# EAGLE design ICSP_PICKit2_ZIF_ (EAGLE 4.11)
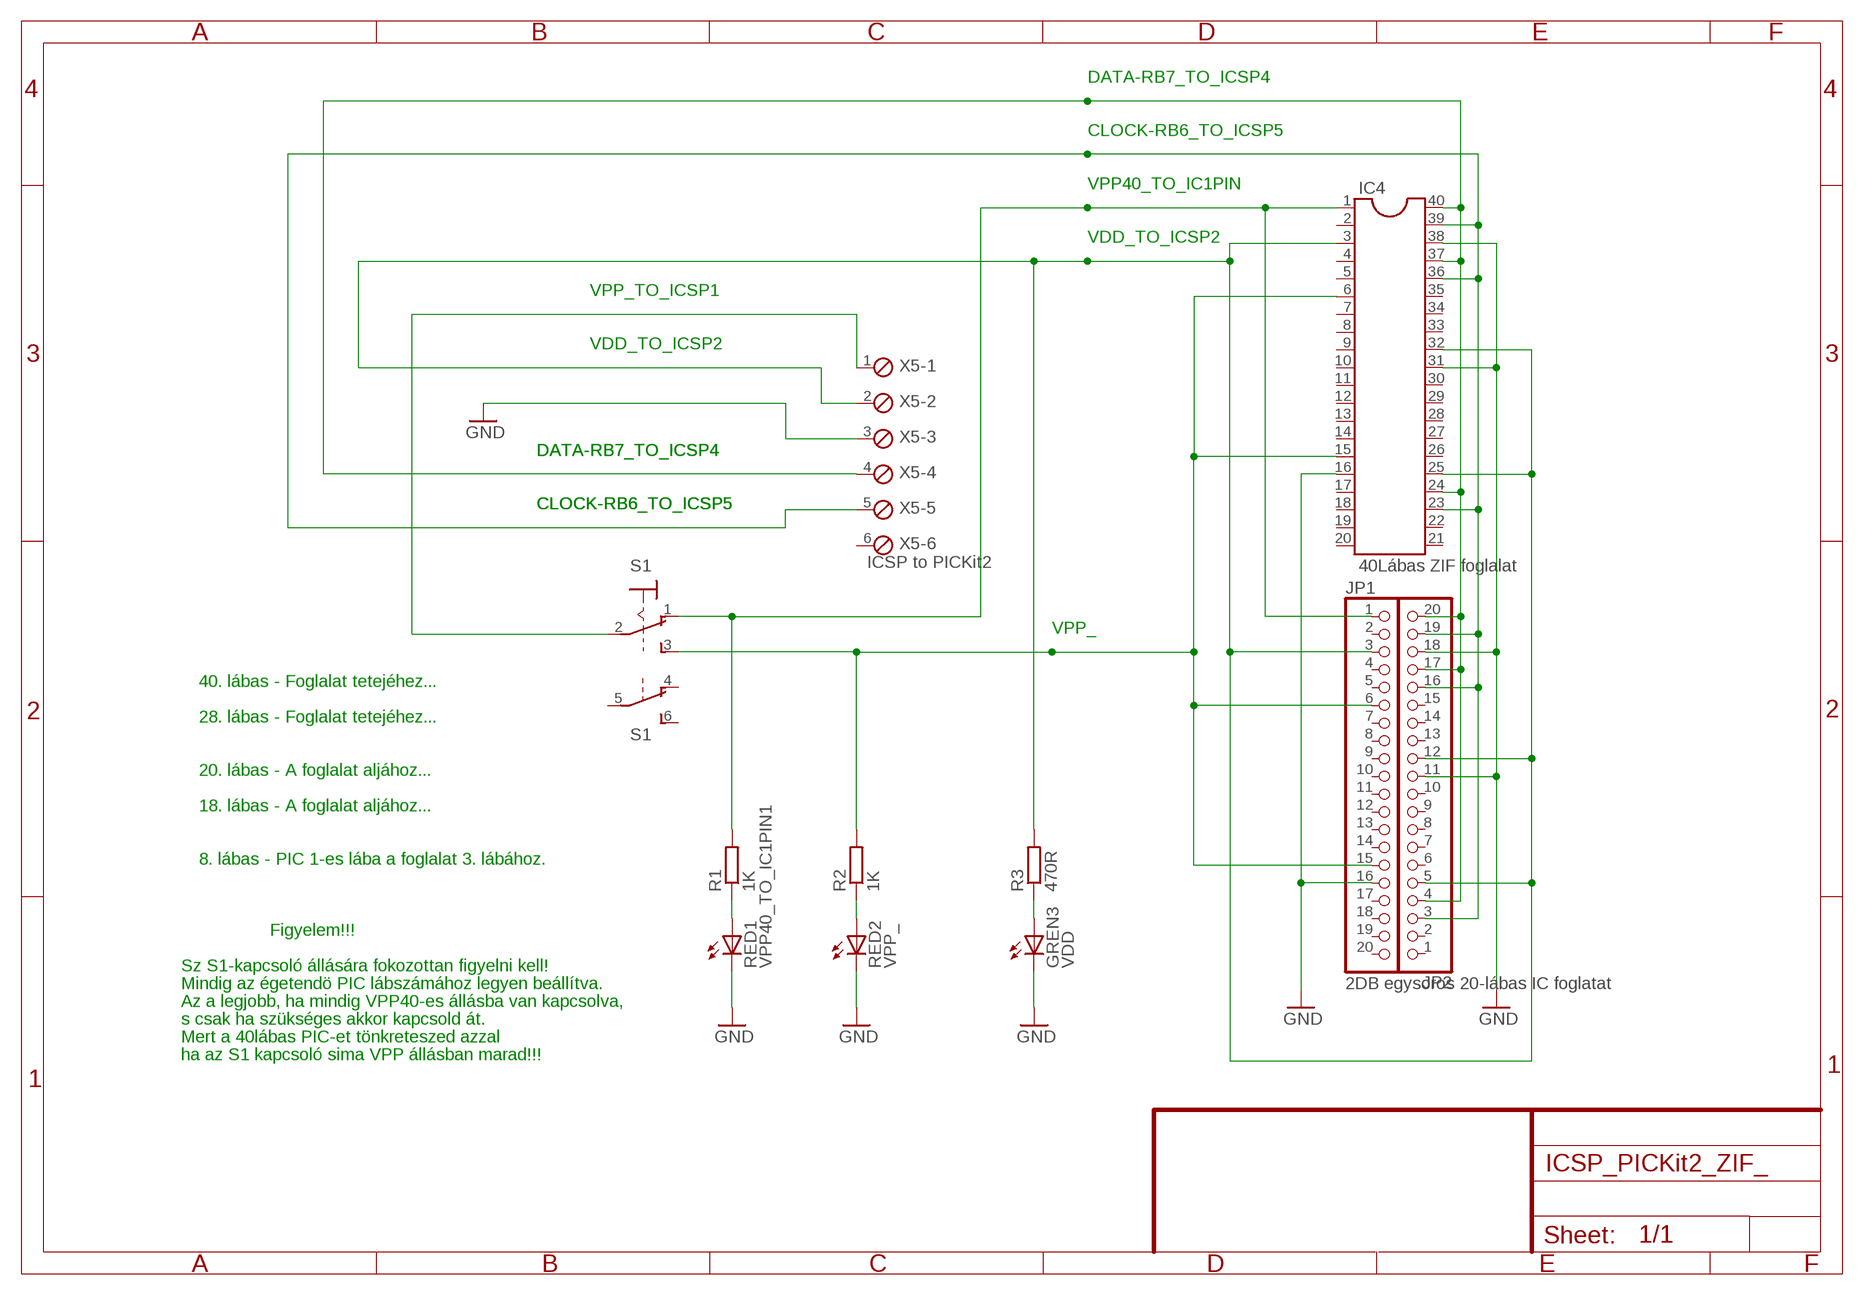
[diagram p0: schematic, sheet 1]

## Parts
GREN3  VDD  LED3MM  [LED3MM]
IC4  40Lábas ZIF foglalat  DIL40  [DIL40]
JP1  2DB egysoros 20-lábas IC foglatat  PINHD-1X20  [1X20]
JP2  PINHD-1X20  [1X20]
R1  1K  R-EU_0204/7  [0204/7]
R2  1K  R-EU_0204/7  [0204/7]
R3  470R  R-EU_0204/7  [0204/7]
RED1  VPP40_TO_IC1PIN1  LED3MM  [LED3MM]
RED2  VPP_  LED3MM  [LED3MM]
S1  320-938  [320-938]
X5  ICSP to PICKit2  MPT6  [6POL254]

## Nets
GND: GREN3.K(C) IC4.16 IC4.31 IC4.38 JP1.16 JP2.11 JP2.18 RED1.K(C) RED2.K(C) X5.3
N$2: IC4.3 IC4.25 IC4.32 JP1.3 JP2.5 JP2.12 R3.2 X5.2
N$5: S1.2(1:P) X5.1
N$6: IC4.1 JP1.1 R1.2 S1.1(1:O)
N$7: IC4.6 IC4.15 JP1.6 JP1.15 R2.2 S1.3(1:S)
N$8: R1.1 RED1.A
N$9: R2.1 RED2.A
N$10: GREN3.A R3.1
N$39: IC4.23 IC4.36 IC4.39 JP2.3 JP2.16 JP2.19 X5.5
N$40: IC4.24 IC4.37 IC4.40 JP2.4 JP2.17 JP2.20 X5.4
Unconnected: IC4.2 IC4.4 IC4.5 IC4.7 IC4.8 IC4.9 IC4.10 IC4.11 IC4.12 IC4.13 IC4.14 IC4.17 IC4.18 IC4.19 IC4.20 IC4.21 IC4.22 IC4.26 IC4.27 IC4.28 IC4.29 IC4.30 IC4.33 IC4.34 IC4.35 JP1.2 JP1.4 JP1.5 JP1.7 JP1.8 JP1.9 JP1.10 JP1.11 JP1.12 JP1.13 JP1.14 JP1.17 JP1.18 JP1.19 JP1.20 JP2.1 JP2.2 JP2.6 JP2.7 JP2.8 JP2.9 JP2.10 JP2.13 JP2.14 JP2.15 S1.4(B:O) S1.5(B:P) S1.6(B:S) X5.6

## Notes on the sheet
- DATA-RB7_TO_ICSP4
- CLOCK-RB6_TO_ICSP5
- VPP40_TO_IC1PIN
- VDD_TO_ICSP2
- VPP_TO_ICSP1
- VDD_TO_ICSP2
- DATA-RB7_TO_ICSP4 | DATA-RB7_TO_ICSP4
- CLOCK-RB6_TO_ICSP5 | CLOCK-RB6_TO_ICSP5 | CLOCK-RB6_TO_ICSP5
- VPP_
- 40. lábas - Foglalat tetejéhez...
- 28. lábas - Foglalat tetejéhez...
- 20. lábas - A foglalat aljához...
- 18. lábas - A foglalat aljához...
- 8. lábas - PIC 1-es lába a foglalat 3. lábához.
- Figyelem!!!
- Sz S1-kapcsoló állására fokozottan figyelni kell!
- Mindig az égetendö PIC lábszámához legyen beállítva.
- Az a legjobb, ha mindig VPP40-es állásba van kapcsolva,
- s csak ha szükséges akkor kapcsold át.
- Mert a 40lábas PIC-et tönkreteszed azzal
- ha az S1 kapcsoló sima VPP állásban marad!!!

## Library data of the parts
GREN3 RED1 RED2 = led:LED: LED
IC4 = ic-package:DIL40: Dual In Line
JP1 JP2 = pinhead:PINHD-1X20: PIN HEADER
R1-R3 = rcl:R-EU_: RESISTOR, European symbol
S1 = switch:320-938: TOGGLE SWITCH distributor RS Components
X5 = con-phoenix-254:MPT6: PHOENIX CONNECTOR

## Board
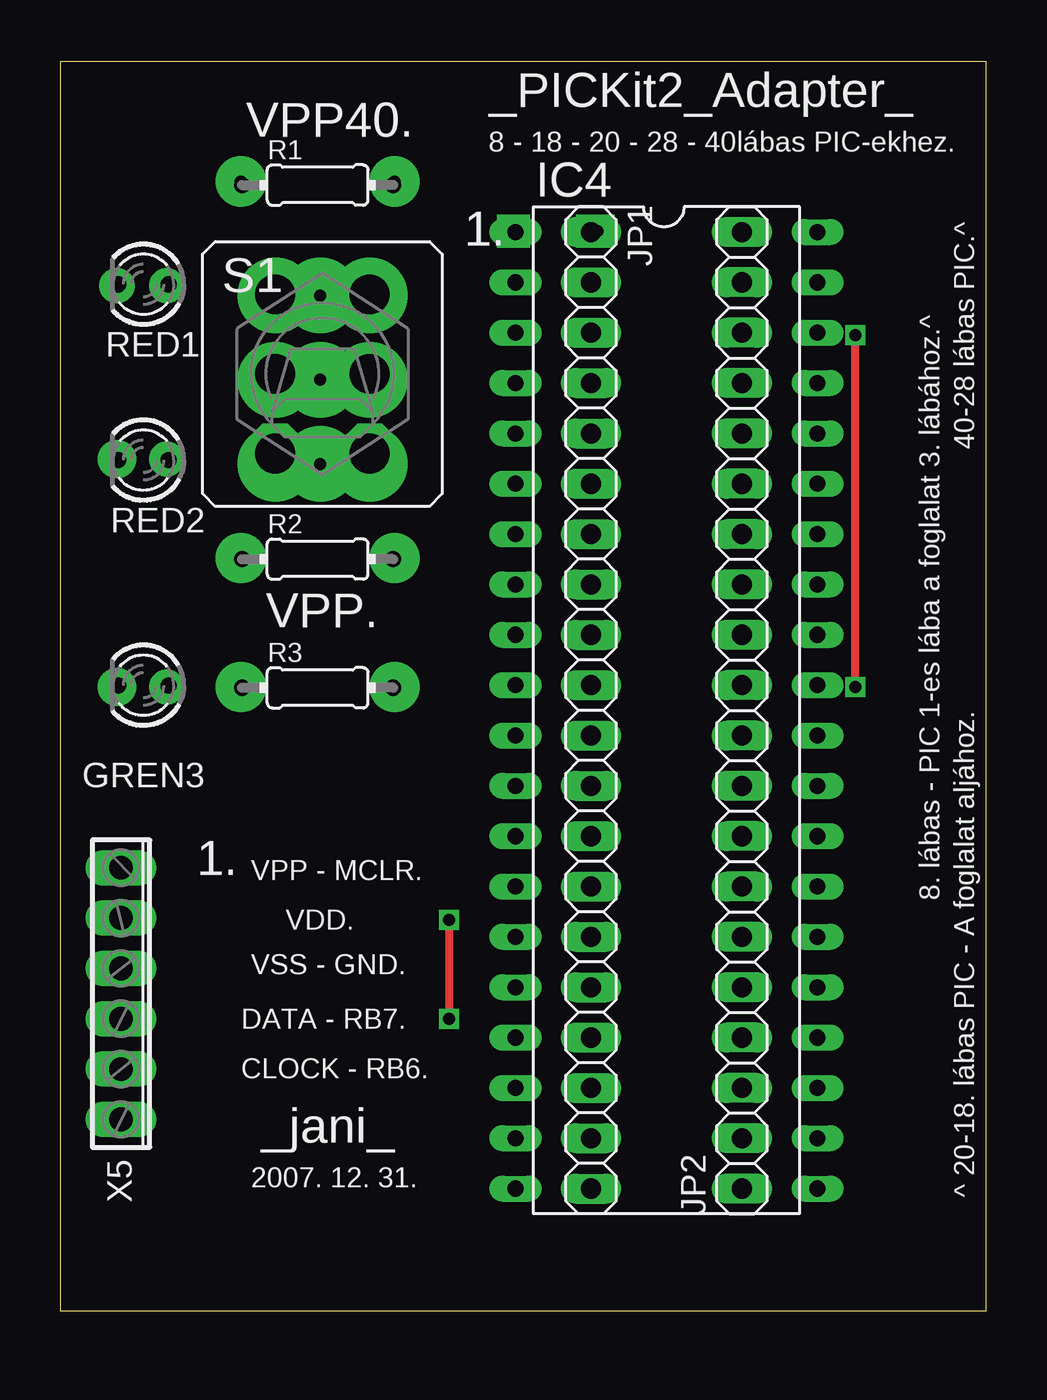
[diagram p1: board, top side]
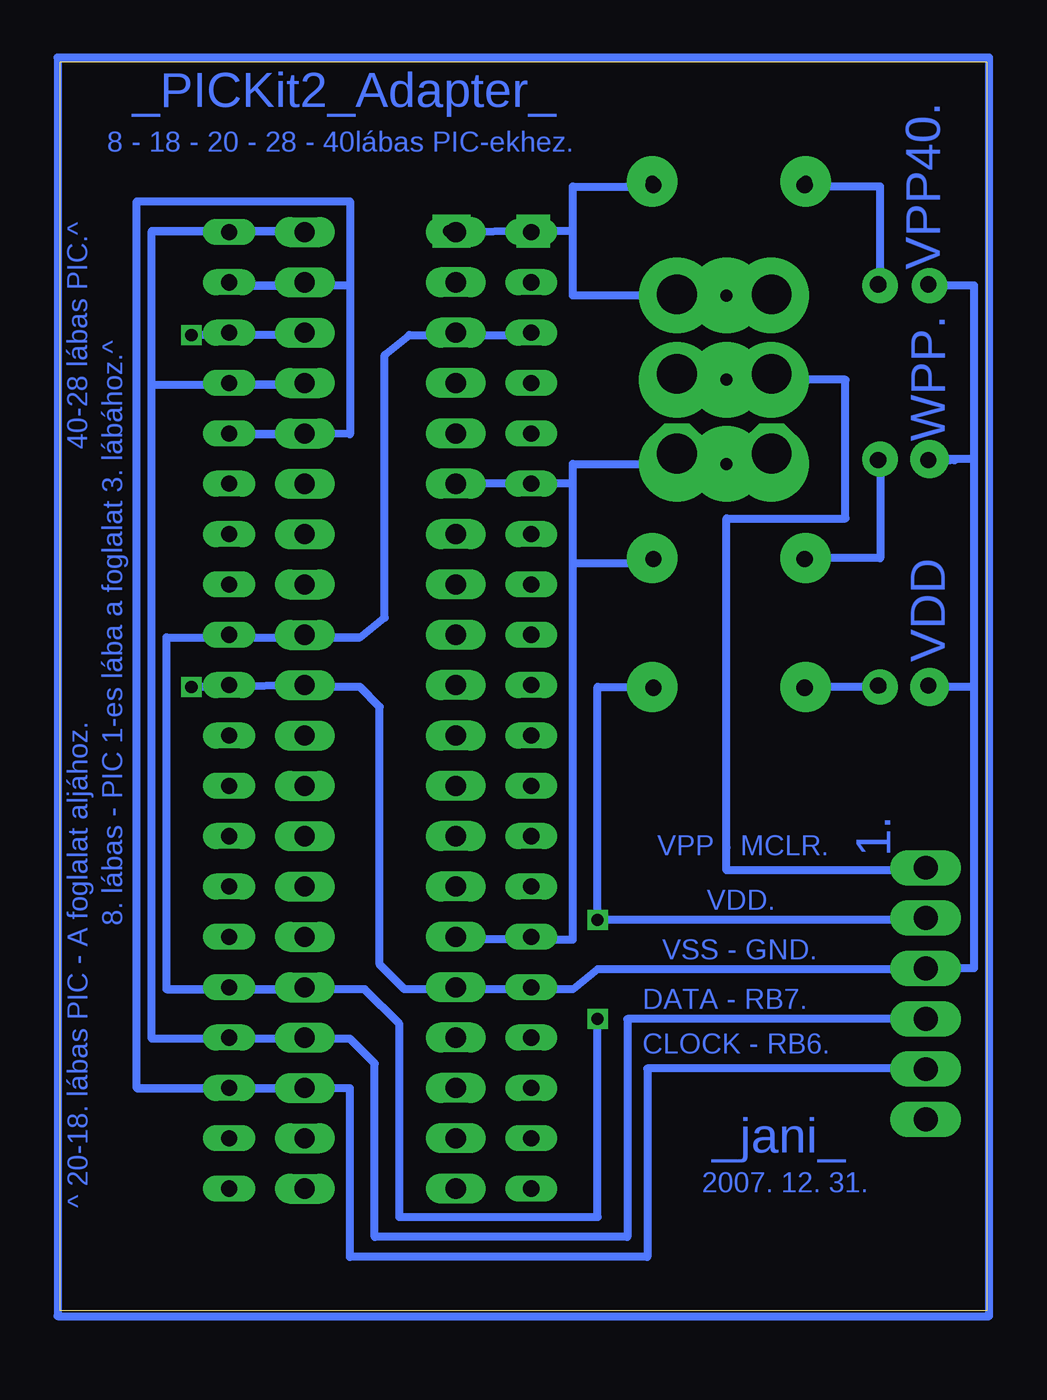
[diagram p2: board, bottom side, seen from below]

Size 46.74 x 63 mm. Coordinates in mm from the lower left corner, seen from the top.
Outline: 0,0 46.74,0 46.74,63 0,63 0,0
Copper layers (1*16): Top 0.035mm / dielectric 1.5mm / Bottom 0.035mm
Design rules "default": minimum track width 10mil, minimum drill 24mil, track to track 8mil, track to pad 8mil, pad to pad 8mil, via to via 8mil, smd to smd 8mil, copper to edge 40mil, drill to drill 8mil, minimum pad ring 10mil, minimum via ring 8mil, stop-mask expansion 4mil, vias tented up to drill 0mil, thermal gap 10mil

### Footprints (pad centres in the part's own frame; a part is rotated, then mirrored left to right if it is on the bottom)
LED3MM = drill 0.813 octagon: A -1.27,0; K 1.27,0
DIL40 = drill 0.813 long: 1 -24.13,-7.62; 2 -21.59,-7.62; 3 -19.05,-7.62; 4 -16.51,-7.62; 5 -13.97,-7.62; 6 -11.43,-7.62; 7 -8.89,-7.62; 8 -6.35,-7.62; 9 -3.81,-7.62; 10 -1.27,-7.62; 11 1.27,-7.62; 12 3.81,-7.62; 13 6.35,-7.62; 14 8.89,-7.62; 15 11.43,-7.62; 16 13.97,-7.62; 17 16.51,-7.62; 18 19.05,-7.62; 19 21.59,-7.62; 20 24.13,-7.62; 21 24.13,7.62; 22 21.59,7.62; 23 19.05,7.62; 24 16.51,7.62; 25 13.97,7.62; 26 11.43,7.62; 27 8.89,7.62; 28 6.35,7.62; 29 3.81,7.62; 30 1.27,7.62; 31 -1.27,7.62; 32 -3.81,7.62; 33 -6.35,7.62; 34 -8.89,7.62; 35 -11.43,7.62; 36 -13.97,7.62; 37 -16.51,7.62; 38 -19.05,7.62; 39 -21.59,7.62; 40 -24.13,7.62
1X20 = drill 1.016 long: 1 -24.13,0; 2 -21.59,0; 3 -19.05,0; 4 -16.51,0; 5 -13.97,0; 6 -11.43,0; 7 -8.89,0; 8 -6.35,0; 9 -3.81,0; 10 -1.27,0; 11 1.27,0; 12 3.81,0; 13 6.35,0; 14 8.89,0; 15 11.43,0; 16 13.97,0; 17 16.51,0; 18 19.05,0; 19 21.59,0; 20 24.13,0
0204/7 = drill 0.813 octagon: 1 -3.81,0; 2 3.81,0
320-938 = drill 2.007 octagon: 1 -2.388,4.013; 2 -2.388,0; 3 -2.388,-4.013; 4 2.388,4.013; 5 2.388,0; 6 2.388,-4.013
6POL254 = drill 1.2 pad 1.778 long: 1 -6.35,0; 2 -3.81,0; 3 -1.27,0; 4 1.27,0; 5 3.81,0; 6 6.35,0

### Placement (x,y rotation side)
GREN3  4.21,31.55 180 top
IC4  30.6,30.29 270 top
JP1  26.79,30.29 270 top
JP2  34.41,30.29 90 top
R1  13,56.79 0 top
R2  13,37.92 0 top
R3  13,31.43 0 top
RED1  4.21,51.78 180 top
RED2  4.21,42.91 180 top
S1  13.24,47.26 0 top
X5  3.08,16 270 top

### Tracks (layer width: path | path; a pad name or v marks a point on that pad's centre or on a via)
GND  (via drill 0.61, 0.61 pad 1.93)
  Top 0.406: v40.13,31.47 v40.13,49.22
  Bottom 0.406: 0.63,31.47 0.63,17.27 X5.3 3.13,17.22 19.63,17.22 20.88,16.22 22.88,16.22 IC4.16 23.13,16.22 26.63,16.22 JP1.16 27.13,16.22 29.38,16.22 30.63,17.47 30.63,30.47 31.63,31.47 34.38,31.47 JP2.11 38.38,31.47 | 2.13,31.55 2.63,31.72 | 2.88,31.55 2.13,31.55 | 2.63,31.47 v2.88,31.47 | 2.63,31.47 2.13,31.47 2.13,31.55 | 2.88,31.55 GREN3.K | 2.63,31.47 2.88,31.55 | 0.63,31.47 2.63,31.47 | 0.63,31.47 0.63,42.97 | 1.63,42.97 v2.88,42.97 1.88,42.91 RED2.K 1.63,42.91 1.63,42.97 | 0.63,42.97 1.63,42.97 | 0.63,42.97 0.63,51.72 2.13,51.72 2.13,51.78 RED1.K | 38.38,31.47 IC4.31 | 38.38,31.47 v40.13,31.47 | 38.13,49.22 v40.13,49.22 | 38.13,49.22 IC4.38 | JP2.18 34.63,49.22 38.13,49.22
N$1  (via drill 0.61 pad 3.81)
  other vias: 13.13,46.97
N$2  (via drill 0.61)
  Top 0.406: v19.63,19.72 v19.63,14.72
  Bottom 0.406: 31.63,33.97 30.38,34.97 30.38,48.22 29.13,49.22 27.38,49.22 JP1.3 26.88,49.22 23.13,49.22 IC4.3 | 31.63,33.97 34.63,33.97 JP2.12 34.88,33.97 38.13,33.97 IC4.32 38.38,33.97 41.38,33.97 | 41.38,16.22 38.38,16.22 IC4.25 37.88,16.22 34.63,16.22 JP2.5 | 41.38,33.97 31.63,33.97 | 41.38,16.22 41.38,33.97 | 41.38,16.22 31.38,16.22 29.63,14.47 29.63,4.72 19.63,4.72 v19.63,14.72 | R3.2 16.88,31.47 19.63,31.47 v19.63,19.72 3.38,19.72 X5.2
N$3  (via drill 0.61 pad 3.81)
  other vias: 13.13,42.72
N$4  (via drill 0.61 pad 3.81)
  other vias: 10.88,42.72
N$5
  Bottom 0.406: S1.2 10.88,46.97 7.13,46.97 7.13,39.97 13.13,39.97 13.13,22.22 3.38,22.22 X5.1
N$6  (via drill 0.61 pad 1.68, 0.61 pad 2.54, 0.61 pad 3.81)
  Bottom 0.406: 20.88,54.47 20.88,56.72 17.88,56.72 R1.2 | 10.63,51.22 11.13,51.22 | 11.13,51.22 v13.13,51.22 13.63,51.47 | 13.63,51.47 16.88,51.22 | 10.63,51.22 v10.88,51.22 11.13,51.22 | S1.1 10.63,51.22 | 22.93,54.47 IC4.1 | 22.93,54.47 JP1.1 | 22.93,54.47 v22.88,54.47 | 20.88,54.47 20.88,51.22 16.88,51.22 | 20.88,54.47 22.93,54.47 | 13.63,50.97 11.13,50.97 | 13.63,50.97 16.88,51.22 | 13.63,51.47 13.63,50.97 | 11.13,51.22 13.63,51.47
N$7
  Bottom 0.406: JP1.6 IC4.6 20.88,41.72 20.88,37.72 | 20.88,37.72 20.88,18.72 22.88,18.72 IC4.15 23.13,18.72 26.88,18.72 JP1.15 | R2.2 17.63,37.72 20.88,37.72 | 20.88,37.72 20.88,42.72 10.88,42.72 S1.3
N$8
  Bottom 0.406: R1.1 8.63,56.72 5.38,56.72 5.38,52.22 RED1.A
N$9  (via drill 0.61 pad 2.54)
  Bottom 0.406: RED2.A 5.38,42.72 5.38,37.97 v9.13,37.97 8.88,37.97 R2.1
N$10
  Bottom 0.406: R3.1 9.13,31.47 5.63,31.47 GREN3.A
N$11  (via drill 0.61 pad 2.54)
  other vias: 9.13,56.97
N$12  (via drill 0.61 pad 2.54)
  other vias: 16.88,56.97
N$13  (via drill 0.61 pad 3.81)
  other vias: 15.63,42.72
N$14  (via drill 0.61 pad 2.54)
  other vias: 16.88,37.97
N$15  (via drill 0.61 pad 2.54, 0.61 pad 3.81)
  other vias: 15.63,51.22 15.63,51.22
N$16  (via drill 0.61 pad 2.54, 0.61 pad 3.81)
  other vias: 15.63,47.22 15.63,46.97
N$17  (via drill 0.61 pad 2.54)
  other vias: 15.63,43.22
N$18  (via drill 0.61 pad 2.54)
  other vias: 10.88,43.22
N$19  (via drill 0.61 pad 2.54)
  other vias: 9.13,31.47
N$20  (via drill 0.61 pad 2.54)
  other vias: 16.88,31.47
N$21  (via drill 0.61 pad 1.68)
  other vias: 22.88,54.47
N$22  (via drill 0.61 pad 1.68)
  other vias: 22.88,54.47
N$25  (via drill 0.61 pad 1.68)
  other vias: 26.88,54.47 27.13,54.47
N$26  (via drill 0.61 pad 1.78)
  other vias: 5.38,51.72
N$27  (via drill 0.61 pad 1.78)
  other vias: 2.88,51.72
N$28  (via drill 0.61 pad 1.78)
  other vias: 5.38,42.97
N$29  (via drill 0.61 pad 1.78)
  other vias: 5.38,31.47
N$39
  Bottom 0.406: 38.13,11.22 35.13,11.22 JP2.3 42.88,11.22 | 38.13,11.22 IC4.23 | 42.88,11.22 38.13,11.22 | 38.13,51.72 IC4.39 | JP2.19 34.88,51.72 38.13,51.72 | JP2.16 34.88,44.22 38.13,44.22 IC4.36 32.13,44.22 32.13,51.72 | 32.13,51.72 32.13,55.97 42.88,55.97 42.88,11.22 | 42.88,11.22 32.13,11.22 32.13,2.72 17.13,2.72 17.13,12.22 3.38,12.22 X5.5 | 32.13,51.72 38.13,51.72
N$40
  Bottom 0.406: 38.38,13.72 34.88,13.72 JP2.4 34.38,13.72 32.13,13.72 30.88,12.47 30.88,3.72 18.13,3.72 18.13,14.72 3.13,14.72 X5.4 | 38.38,13.72 IC4.24 | 38.38,13.72 42.13,13.72 42.13,46.72 | 38.38,46.72 IC4.37 37.88,46.72 34.88,46.72 | 34.88,46.72 JP2.17 | JP2.20 34.63,54.47 34.88,54.47 | 34.88,54.47 38.13,54.47 IC4.40 38.38,54.47 42.13,54.47 | 42.13,46.72 34.88,46.72 | 34.88,54.47 42.13,54.47 | 42.13,46.72 42.13,54.47
N$41  (via drill 0.61 pad 3.81)
  other vias: 10.88,46.97
N$43
  Bottom 0.406: -0.12,63.22 46.88,63.22 46.88,-0.28 -0.12,-0.28 -0.12,63.22

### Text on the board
Bottom: VPP40. | _PICKit2_Adapter_ | 8 - 18 - 20 - 28 - 40lábas PIC-ekhez. | WPP. | 8. lábas - PIC 1-es lába a foglalat 3. lábához.^ | 40-28 lábas PIC.^ | VDD | ^ 20-18. lábas PIC - A foglalat aljához. | 1. | VPP - MCLR. | VDD. | VSS - GND. | DATA - RB7. | CLOCK - RB6. | _jani_ | 2007. 12. 31.
tPlace: _PICKit2_Adapter_ | VPP40. | 8 - 18 - 20 - 28 - 40lábas PIC-ekhez. | 1. | 40-28 lábas PIC.^ | VPP. | 1. | VPP - MCLR. | 8. lábas - PIC 1-es lába a foglalat 3. lábához.^ | VDD. | VSS - GND. | DATA - RB7. | CLOCK - RB6. | _jani_ | 2007. 12. 31. | ^ 20-18. lábas PIC - A foglalat aljához.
